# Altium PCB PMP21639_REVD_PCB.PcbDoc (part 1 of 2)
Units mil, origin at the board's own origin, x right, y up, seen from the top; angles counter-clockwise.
Board outline 3667.52 x 1155.04 mil, 4 copper layers (Top Layer, Signal Layer 1, Signal Layer 2, Bottom Layer), stack 90.224 mil thick; 122 components, 73 nets, 372 pads, 102 vias.
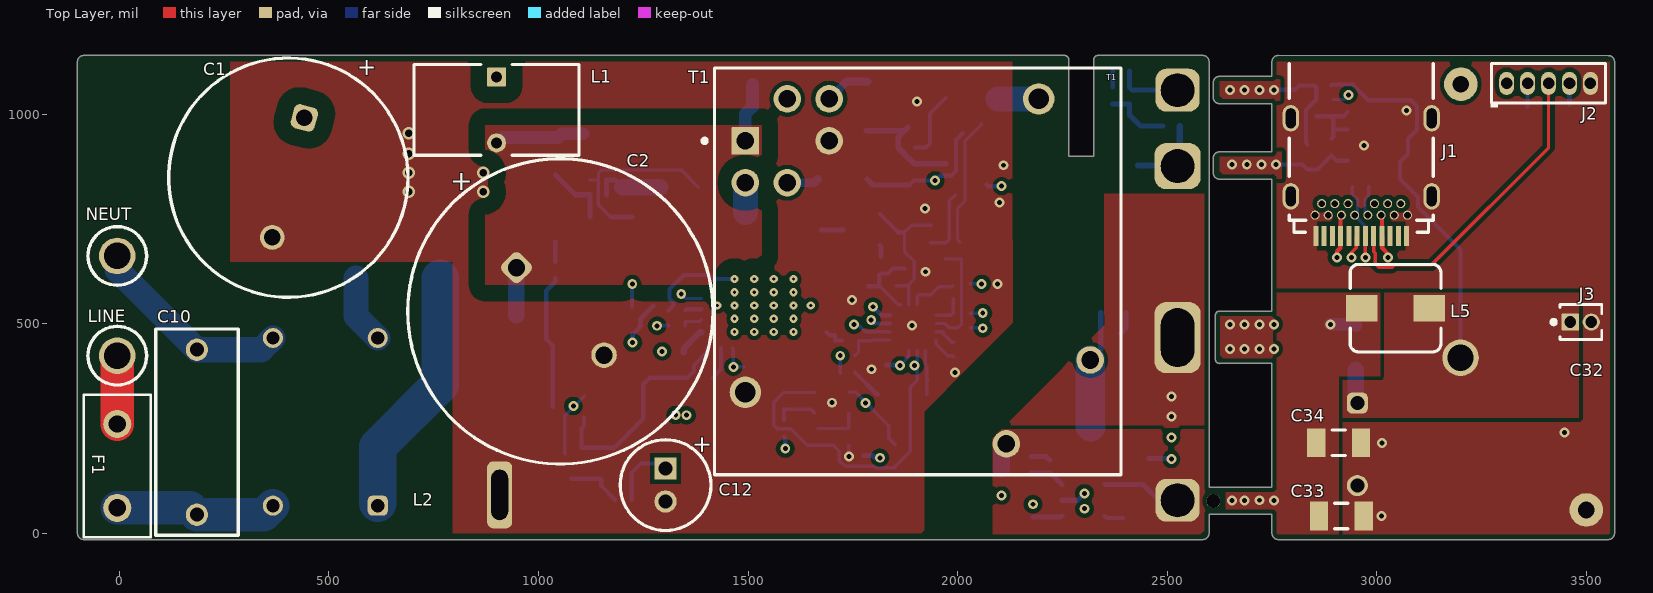
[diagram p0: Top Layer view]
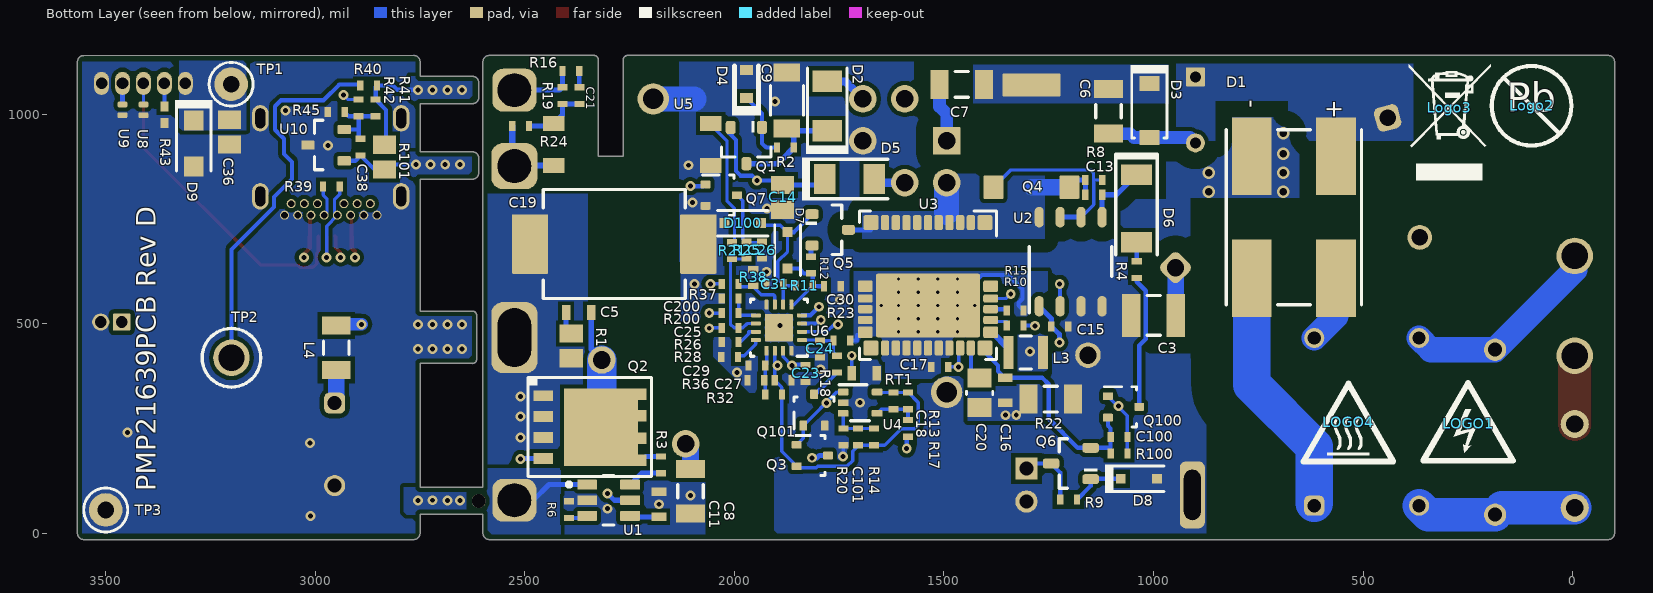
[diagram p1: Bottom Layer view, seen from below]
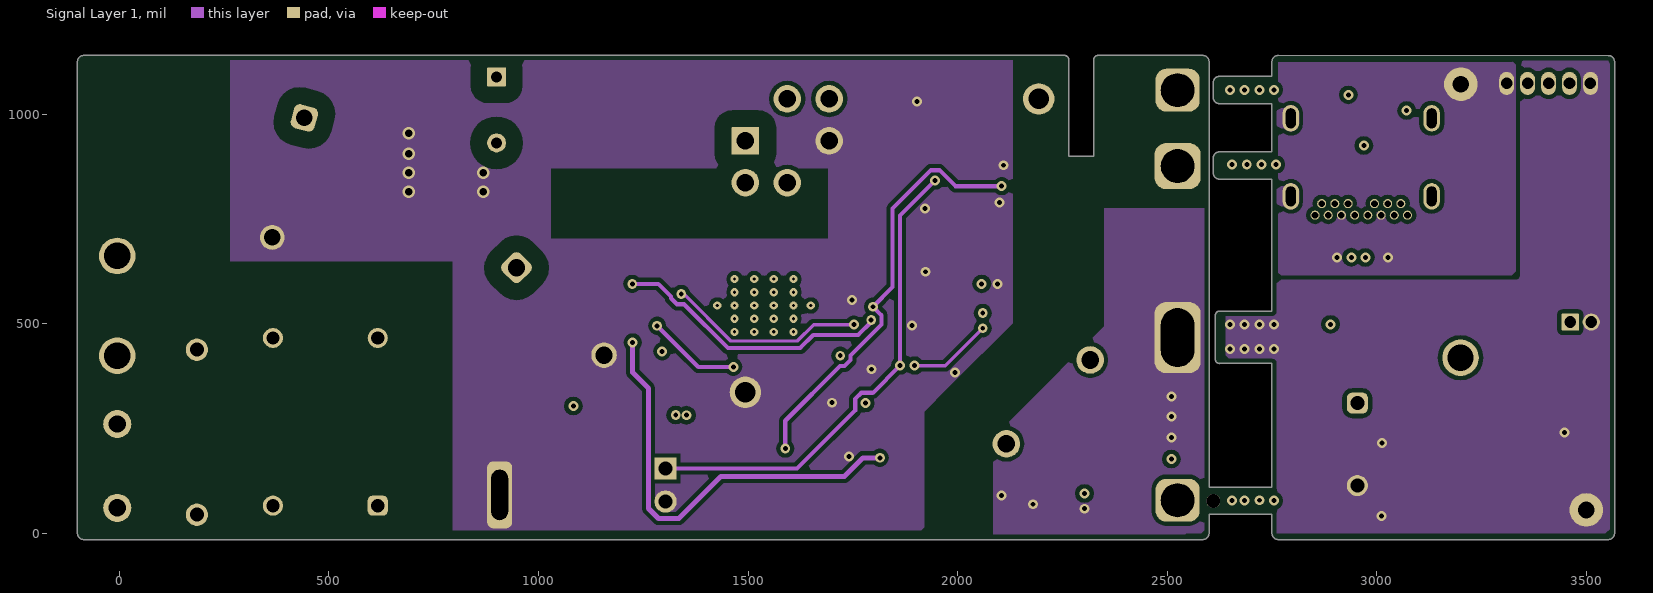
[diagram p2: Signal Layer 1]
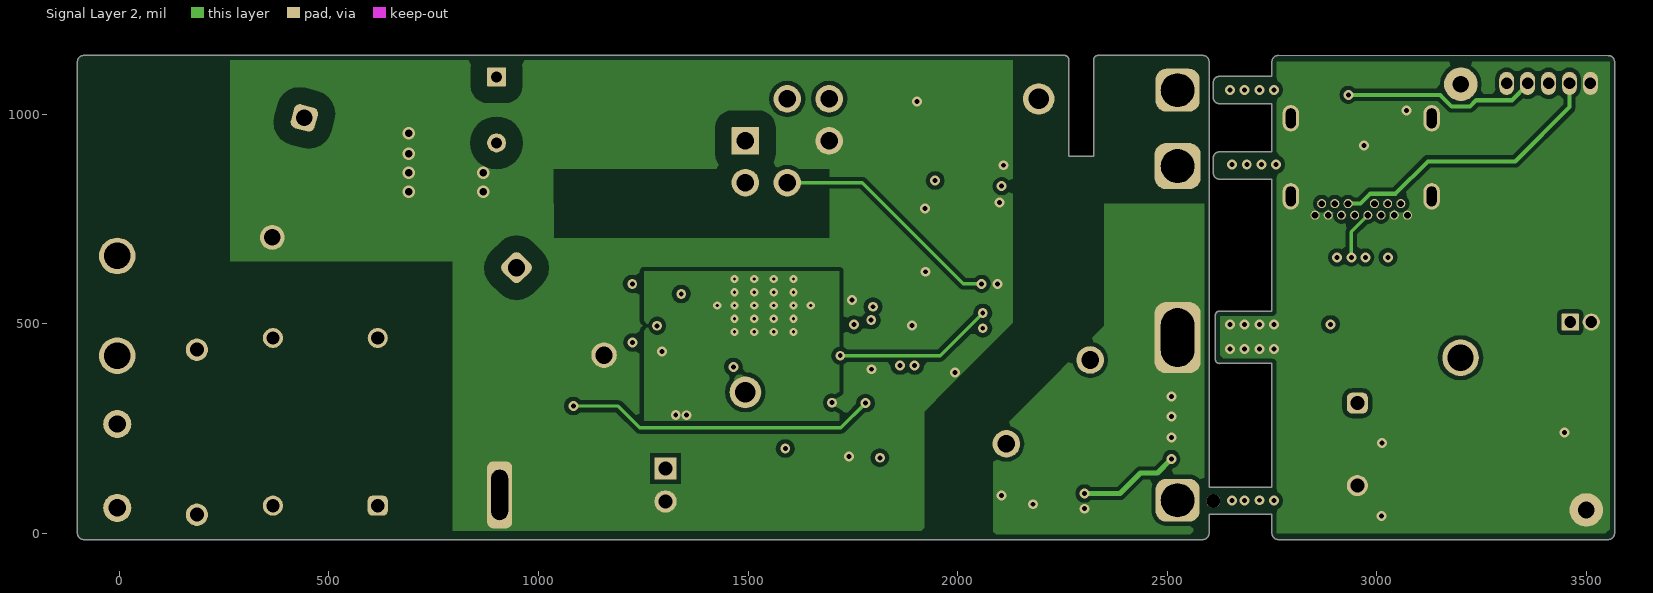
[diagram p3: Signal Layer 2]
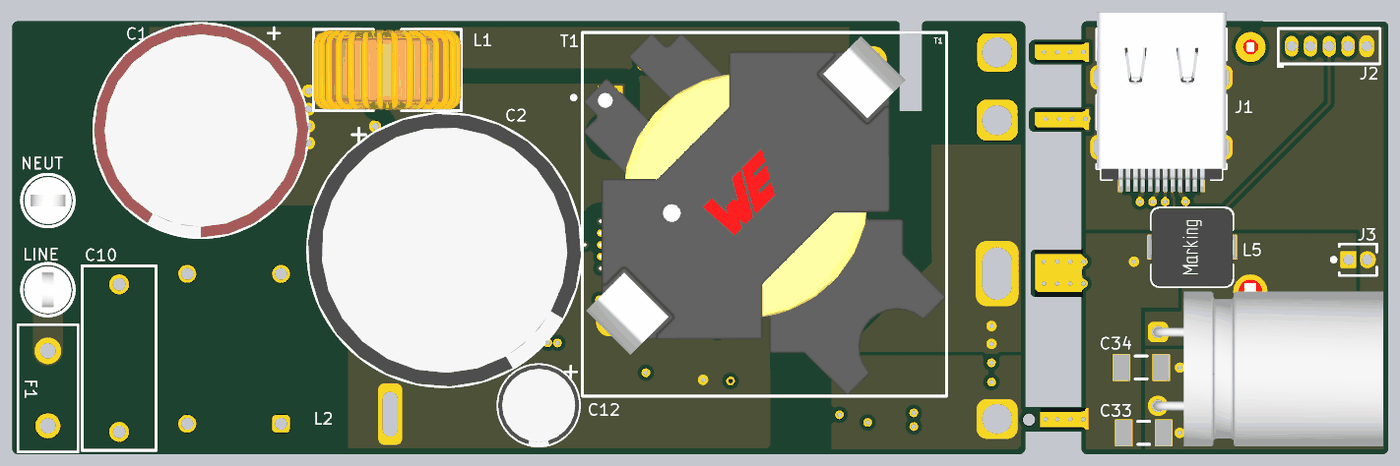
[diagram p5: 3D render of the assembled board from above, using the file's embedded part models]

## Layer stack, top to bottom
Top Solder: solder mask 0.4, Solder Resist, Dk 3.5
Top Layer: signal copper 2.7559
Dielectric 2: dielectric 10, Dk 4.2
Signal Layer 1: signal copper 2.7559
Dielectric 3: dielectric 10, Dk 4.2
Signal Layer 2: signal copper 2.7559
Dielectric1: core 59.2, FR-4, Dk 4.8
Bottom Layer: signal copper 2.7559
Bottom Solder: solder mask 0.4, Solder Resist, Dk 3.5

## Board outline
-85,-15.02 cw(c-85,0) -100.02,0 -100,0 -100,1125 -100.02,1125 cw(c-85,1125) -85,1140.02 2255,1140.02 cw(c2255,1130) 2265.02,1130 2265.02,900 2324.98,900 2324.98,1130 cw(c2335,1130) 2335.69,1139.99 2336.3,1140.02 2585,1140.02 cw(c2585,1125) 2600.02,1125 2600,1125 2600,110 2749.98,110 2749.98,405 2625,405 2625,404.98 cw(c2625,415) 2614.98,415 2614.98,520 cw(c2625,520) 2625,530.02 2625,530 2749.98,530 2749.98,845 2625,845 2625,844.98 cw(c2625,860) 2609.98,860 2609.98,895 cw(c2625,895) 2625,910.02 2625,910 2749.98,910 2749.98,1025 2625,1025 2625,1024.98 cw(c2625,1040) 2609.98,1040 2609.98,1075 cw(c2625,1075) 2625,1090.02 2625,1090 2749.98,1090 2749.98,1125 cw(c2765,1125) 2765,1140.02 3552.48,1139.64 cw(c3552.48,1124.62) 3567.5,1124.62 3567.5,0 cw(c3552.48,0) 3552.48,-15.02 2765,-15.02 cw(c2765,0) 2749.98,0 2749.98,45 2600,45 2600,0 2600.02,0 cw(c2585,0) 2585,-15.02

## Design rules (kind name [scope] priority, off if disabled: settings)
AcuteAngle [All] p1 off: minimum=4.50000000000000E+0001 checktracksonly=FALSE
AssemblyTestPointUsage [All] p1: valid=2
BoardOutlineClearance BoardOutlineClearance_MountingHoles [OnCopper and InComponentClass('Mounting Holes')] p1: gap=11.81 ignorepadtopadclearanceinfootprint=FALSE
BoardOutlineClearance BoardOutlineClearance_Poly [OnCopper and IsPoly] p2: gap=11.81 ignorepadtopadclearanceinfootprint=FALSE
BoardOutlineClearance [OnCopper and Not InComponentClass('Logo') and not InComponentClass('FiducialMark') and not InRegion(1000,500,4000,800) and not InPoly] p3: gap=10 ignorepadtopadclearanceinfootprint=FALSE
Clearance "Clearance VAC to PGND" [InNetClass('VAC') vs InNetClass('PGND')] p1: gap=100 ignorepadtopadclearanceinfootprint=TRUE
Clearance "Clearance VSW to HV" [InNetClass('Switch Node') vs InNetClass('High Voltage')] p2: gap=34 ignorepadtopadclearanceinfootprint=FALSE
Clearance Clearance_Safety [InNetClass('PGND') vs InNetClass('SGND')] p3: gap=160 ignorepadtopadclearanceinfootprint=FALSE
Clearance "Clearance VSW to PGND" [InNetClass('Switch Node') vs InNetClass('PGND')] p4: gap=34 ignorepadtopadclearanceinfootprint=FALSE
Clearance Clearance_HV [InNetClass('High Voltage') vs InNetClass('PGND')] p5: gap=40 ignorepadtopadclearanceinfootprint=FALSE
Clearance Clearance_Keepouts [((IsTrack Or IsArc) And Not InPoly) And IsFree and IsKeepOut vs ((IsTrack Or IsArc) And Not InPoly) And IsFree and IsKeepOut] p6: gap=0 ignorepadtopadclearanceinfootprint=FALSE
Clearance Clearance_Poly [InPolygon] p7: gap=10 ignorepadtopadclearanceinfootprint=FALSE except(0: Arc-Hole Track-Hole SMDPad-Hole THPad-Hole Via-Hole Fill-Hole Poly-Hole Region-Hole Text-Hole)
Clearance [All] p8: gap=7.87 ignorepadtopadclearanceinfootprint=TRUE except(0: Arc-Hole Track-Hole SMDPad-Hole THPad-Hole Via-Hole Fill-Hole Poly-Hole Region-Hole Text-Hole)
ComponentClearance ComponentClearance_MountingHoles_FiducialMarks [InComponentClass('Mounting Holes') vs InComponentClass('FiducialMark')] p1: gap=50 collisioncheckmode=3 verticalgap=10 showdistances=FALSE
ComponentClearance ComponentClearance_Shunt [InComponentClass('Header') vs InComponentClass('Shunt')] p2 off: gap=0 collisioncheckmode=3 verticalgap=0 showdistances=FALSE
ComponentClearance ComponentClearance_Logo [InComponentClass('Logo')] p3 off: gap=50 collisioncheckmode=3 verticalgap=10 showdistances=FALSE
ComponentClearance ComponentClearance_ScrewToNut [(HasFootprint('NY PMS 440 0025 PH')) vs (HasFootprint('Keystone_1902C'))] p4 off: gap=5 collisioncheckmode=3 verticalgap=10 showdistances=FALSE
ComponentClearance ComponentClearance_MountingHoles [InComponentClass('Mounting Holes')] p5 off: gap=250 collisioncheckmode=3 verticalgap=100000 showdistances=FALSE
ComponentClearance ComponentClearance_SmallPassives [HasFootprint('0201*') or HasFootprint('0402*') or HasFootprint('0508') or HasFootprint('0603*') or HasFootprint('0612') or HasFootprint('0805*') or HasFootprint('0815*') or HasFootprint('0830*') or HasFootprint('1206*') or HasFootprint('1210*') or HasFootprint('1808*') or HasFootprint('1812*') or HasFootprint('1825*') or HasFootprint('2010*') or HasFootprint('2220*') or HasFootprint('2225*') or HasFootprint('2512*') or HasFootprint('2728*') or HasFootprint('3518*') vs HasFootprint('0201*') or HasFootprint('0402*') or HasFootprint('0508') or HasFootprint('0603*') or HasFootprint('0612') or HasFootprint('0805*') or HasFootprint('0815*') or HasFootprint('0830*') or HasFootprint('1206*') or HasFootprint('1210*') or HasFootprint('1808*') or HasFootprint('1812*') or HasFootprint('1825*') or HasFootprint('2010*') or HasFootprint('2220*') or HasFootprint('2225*') or HasFootprint('2512*') or HasFootprint('2728*') or HasFootprint('3518*')] p6: gap=10 collisioncheckmode=3 verticalgap=10 showdistances=FALSE
ComponentClearance ComponentClearance_THtoSMT [IsThruComponent vs IsSMTComponent] p7: gap=10 collisioncheckmode=3 verticalgap=10 showdistances=FALSE
ComponentClearance ComponentClearance_THtoTH [IsThruComponent vs IsThruComponent] p8: gap=10 collisioncheckmode=3 verticalgap=30 showdistances=FALSE
ComponentClearance [All] p9: gap=-39.37 collisioncheckmode=3 verticalgap=-39.37 showdistances=FALSE
DiffPairsRouting [All] p1: maxlimit=100 minlimit=10 mostfreqgap=10 toplayer_minwidth=15 toplayer_maxwidth=15 toplayer_prefwidth=15 midlayer1_minwidth=15 midlayer1_maxwidth=15 midlayer1_prefwidth=15 midlayer2_minwidth=15 midlayer2_maxwidth=15 midlayer2_prefwidth=15 bottomlayer_minwidth=15 bottomlayer_maxwidth=15 bottomlayer_prefwidth=15 maxuncoupledlength=1000
FabricationTestPointUsage TestPointUsage [All] p1: valid=2 allowmultiple=FALSE
FabricationTestpoint Testpoint [All] p1: side=3 testpointundercomponent=TRUE minsize=40 maxsize=100 preferedsize=60 minholesize=0 maxholesize=40 preferedholesize=32 testpointgrid=1 allowsidetop=TRUE allowsidebottom=TRUE usegrid=TRUE gridtolerance=0.01
FanoutControl Fanout_LCC [IsLCC] p1: bgadir=Out bgaviamode=Centered fanoutstyle=Auto fanoutdirection=Alternating viagrid=1 // Fanout_LCC (Default Rule)
FanoutControl Fanout_BGA [IsBGA] p2: bgadir=Out bgaviamode=Centered fanoutstyle=Auto fanoutdirection=Alternating viagrid=1 // Fanout_BGA (Default Rule)
FanoutControl Fanout_Default [All] p4: bgadir=Out bgaviamode=Centered fanoutstyle=Auto fanoutdirection=Alternating viagrid=1 // Fanout_Default (Default Rule)
FanoutControl Fanout_Small [(CompPinCount < 5)] p5: bgadir=Out bgaviamode=Centered fanoutstyle=Auto fanoutdirection=OutThenIn viagrid=1 // Fanout_Small (Default Rule)
HoleSize [All] p1: absolutevalues=TRUE maxlimit=251 minlimit=7.87 maxpercent=80.000 minpercent=20.000
MinimumAnnularRing MinimumAnnularRing_ThermalPadVias [IsVia and InAnyComponent] p1: minimumring=5.91
MinimumAnnularRing [All] p2: minimumring=2.9
MinimumSolderMaskSliver MinimumSolderMaskSliver_Logo [InComponentClass('Logo') vs InComponentClass('Logo')] p1 off: minsoldermaskwidth=0.7
MinimumSolderMaskSliver [All] p2 off: minsoldermaskwidth=3.94
PlaneConnect [All] p1: planeconnectstyle=Relief reliefexpansion=10 reliefentries=4 reliefconductorwidth=10 reliefairgap=10
PolygonConnect [All] p1: connectstyle=Direct reliefconductorwidth=10 reliefentries=4 polygonreliefangle="90 Angle" airgapwidth=10
RoutingVias ThermalPadVias [IsVia and InAnyComponent] p1: holewidth=7.87 width=19.68 viastyle="Through Hole" minholewidth=7.87 minwidth=19.68 maxholewidth=12.99 maxwidth=23.62
RoutingVias [All] p2: holewidth=16 width=34 viastyle="Through Hole" minholewidth=7.87 minwidth=22 maxholewidth=40 maxwidth=65
SilkToBoardRegionClearance [Not ((IsComment or IsDesignator) And (Hide <> 'False')) and not InRegion(1000,500,4000,800)] p1:
SilkToSilkClearance SilkToSilkClearance_Pb-FreeLogo [(HasFootprint('Pb-Free_Overlay_Medium') OR HasFootprint('Pb-Free_Overlay_Small')) vs (HasFootprint('Pb-Free_Overlay_Medium') OR HasFootprint('Pb-Free_Overlay_Small'))] p1: silktosilkclearance=0
SilkToSilkClearance [All] p2: silktosilkclearance=1
SilkToSolderMaskClearance SilkToComponentPadClearance [(IsPad or IsFill or IsRegion) and InAnycomponent] p1: minsilkscreentomaskgap=0.1 clearancetoexposedcopper=TRUE
SilkToSolderMaskClearance "Silk to Solder Mask Opening" [All] p2: minsilkscreentomaskgap=0.1 clearancetoexposedcopper=FALSE
SolderMaskExpansion [All] p1: expansion=1.97
Width [All] p1: maxlimit=100 minlimit=6 preferedwidth=10 checkconnectedcopper=TRUE
15 further rules are at their usual default settings.

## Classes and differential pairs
net class VAC: NetC10_1 NetC10_2 NetD1_2 NetD1_3 NetF1_2
net class "Switch Node": NetC13_1 NetQ4_1 VSW
net class SGND: NetC5_1 NetC5_2 S1 SGND1
component class Header: J2 J3
component class PMP21639_REVD_pg2: C32 C33 C34 C36 C38 D9 J1 J2 J3 L4 L5 R39 R40 R41 R42 R43 R45 R101 TP1 TP2 TP3 U8 U9 U10
net class PGND: NetC16_2 PGND VS
net class "High Voltage": NetC1_1 NetC2_1 NetC6_2
component class PMP21639_REVD_pg1: C1 C2 C3 C5 C6 C7 C8 C9 C10 C11 C12 C13 C14 C15 C16 C17 C18 C19 C20 C21 C22 C23 C24 C25 C26 C27 C29 C30 C31 C100 C101 C200 D1 D2 D3 D4 D5 D6 D7 D8 D100 F1 L1 L2 L3 LINE LOGO1 Logo2 Logo3 LOGO4 NEUT Q1 Q2 Q3 Q4 Q5 Q6 Q7 Q100 Q101 R1 R2 R3 R4 R6 R8 R9 R10 R11 R12 R13 R14 R15 R16 R17 R18 R19 R20 R21 R22 R23 R24 R25 R26 R28 R32 R36 R37 R38 R100 R200 RT1 T1 U1 U2 U3 U4 U5 U6

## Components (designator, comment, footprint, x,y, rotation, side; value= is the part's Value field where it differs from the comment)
C1 "EKXJ401ELL390MU20S" Chemi-Con_1450x2000 403.05,848.39 r255 top value=39uF
C2 "400BXW68MEFC18X20" BXW_1800x2000 1052.06,529.4 r315 top value=68uF
C3 "C1210W104KCRACTU" 1210_230L 1000,520 r0 bottom value=0.1uF
C5 "C1608C0G2E221J080AA" 0603S 2371.54,526.5 r180 bottom value=220pF
C6 "CGA5L3X7T2E224K160AE" 1206L 1107.24,1006.66 r90 bottom value=0.22uF
C7 "CGA5L3X7T2E224K160AE" 1206L 1457.44,1071.13 r180 bottom value=0.22uF
C8 "C3216X5R1E336M160AC" 1206_180L 2105,100.39 r270 bottom value=33uF
C9 "C3216X7R2A474K160AA" 1206_180 1874.85,1032.74 r270 bottom value=0.47uF
C10 "BFC242042203" CAPRR1000W60L1250T500H1100 185,241.01 r270 top value=0.1uF
C11 "GRM188R61E105KA12D" 0603S 2180,69.2 r90 bottom value=1uF
C12 "ECA1HM220" Panasonic_500x1100 1303.15,115 r270 top value=22uF
C13 "GRM155R71E473KA88D" 0402S 1142.68,807.6 r0 bottom value=0.047uF
C14 "C2012X7R1H105K085AC" 0805L 1885,801.47 r90 bottom value=1uF
C15 "GRM155R71E103KA01D" 0402S 1223.8,493.78 r180 bottom value=0.01uF
C16 "GRM188R61E105KA12D" 0603S 1353.5,341.16 r270 bottom value=1uF
C17 "GRM155R71H223KA12D" 0402S 1510,397 r180 bottom value=0.022uF
C18 "GRM155R71C472KA01D" 0402S 1620,315.82 r270 bottom value=4700pF
C19 "DK1E3EA152M86RAH01" DK1_86 2286.81,690 r180 bottom value=1500pF
C20 "08053C225KAT2A" 0805_150 1415,335 r270 bottom value=2.2uF
C21 "GRM155R72A332KA01D" 0402S 2370,1044.1 r270 bottom value=3300pF
C23 "GRM155R61H104ME14D" 0402S 1830.29,381.46 r270 bottom value=0.1uF
C24 "GRM1555C1H101JA01D" 0402S 1795.86,439.68 r90 bottom value=100pF
C25 "GRM1555C1H101JA01D" 0402S 2010,490 r0 bottom value=100pF
C26 "GRM1555C1H180JA01D" 0402S 1934.2,675.32 r270 bottom value=18pF
C27 "C1005X7R1H104K050BB" 0402S 1883.82,365 r180 bottom value=0.1uF
C29 "C1005C0G1H221F050BA" 0402S 1946.22,400 r0 bottom value=220pF
C30 "GRM1555C1H220FA01D" 0402S 1766.34,589.25 r180 bottom value=22pF
C31 "GRM155R71H222KA01D" 0402S 1903.5,594.02 r0 bottom value=2200pF
C32 "687AVG025MGBJ" AVG_1000x1200_HU 2953.76,212.04 r270 top value=680uF
C33 "C3216X5R1E336M160AC" 1206_180L 2915.87,41.34 r0 top value=33uF
C34 "C3216X5R1E336M160AC" 1206_180L 2908.98,215.94 r0 top value=33uF
C36 "C2012X5R1E685K125AC" 0805L 3205,957.02 r270 bottom value=6.8uF
C38 "GRM155R71E103KA01D" 0402S 2891.99,921.12 r270 bottom value=0.01uF
C100 "GRM155R71H222KA01D" 0402S 1082.31,230.01 r180 bottom value=2200pF
C101 "GRM155R71H102KA01D" 0402S 1705,230 r90 bottom value=1000pF
C200 "GRM1555C1H101JA01D" 0402S 2010,560 r180 bottom value=100pF
D1 "Z4DGP406L-HF" Z4-D 665,754.17 r270 bottom value=600V
D2 "CSFMT104-HF" SOD-123H 1778.5,1019.33 r90 bottom value=200V
D3 "SMF100A" SOD-123FL 1010,1008.63 r270 bottom value=100V
D4 "CZRU52C15" SOD-523F 1971.14,1071.97 r90 bottom value=15V
D5 "CSFMT104-HF" SOD-123H 1725,845 r180 bottom value=200V
D6 "ES1JAF" SMAF 1040.62,775 r270 bottom value=600V
D7 "CDSOD323-T18C" SOD-323-Bi 1873.23,675 r90 bottom value=18V
D8 "13V" SOD-323 1035,130 r180 bottom
D9 "PMEG4030ER,115" SOD-123W 3290,929.96 r270 bottom value=40V
D100 "CDSOD323-T18C" SOD-323-Bi 1980.32,740 r180 bottom value=18V
F1 "39213150000" FUSE_392 -5,160.5 r90 top
J1 "632 723 300 011" Wurth_632_723_300_011 2963.11,1125.83 r180 top
J2 "GRPB051VWVN-RC" Sullins_GRPB051VWVN-RC 3410,1073.49 r0 top
J3 "GRPB021VWVN-RC" Sullins_GRPB021VWVN-RC 3486.93,503.77 r0 top
L1 "7447052" FP-7447052_PTH_D10MM0-MFG 900,1010 r0 top
L2 "RLTI-1301" Renco_RLTI-1301 491.5,265.83 r180 top value=1.3mH
L3 "BRC2518T220K" 1007 1305,431.22 r0 bottom value=22uH
L4 "74479136" 1206L 2950,442.4 r270 bottom value=0.68uH
L5 "744316100" WE-HCI_5040 3045,536.93 r90 top value=1uH
LINE "5012" Keystone5012 -5,423.61 r0 top
LOGO1 "DANGER HIGH VOLTAGE" IEC_HighVoltage_Small 249.51,260.9 r180 bottom
Logo2 "Pb-Free Symbol" Pb-Free_Overlay_Medium 98,1020 r180 bottom
Logo3 "WEEE logo" WEEE_Minimum 295,1015 r180 bottom
LOGO4 "CAUTION HOT SURFACE" IEC_HotSurface_Small 535,264.51 r180 bottom
NEUT "5012" Keystone5012 -5,661.66 r90 top
Q1 "BSS123" SOT-23L 1971.61,925.05 r270 bottom value=100V
Q2 "BSC093N15NS5ATMA1" PG-TDSON-8 2345,253.34 r180 bottom value=150V
Q3 "BSS223PWH6327" SOT-323 1814.04,185.44 r180 bottom value=-20V
Q4 "IPN60R1K0CEATMA1" FP-IPN60R1K0CEATMA1_SOT223-3-MFG 1291.22,947.6 r90 bottom
Q5 "BSS126H6327XTSA2" SOT-23L 1771.22,723.93 r180 bottom value=600V
Q6 "BSS138" SOT-23 1197.24,166.42 r0 bottom value=50V
Q7 "2N7002KW" SOT-323 2031.45,806.67 r180 bottom value=60V
Q100 "BSS223PWH6327" SOT-323 1071.53,301.49 r180 bottom value=-20V
Q101 "2N7002KW" SOT-323 1810,294.18 r90 bottom value=60V
R1 "CRCW080522R0JNEA" 0805L 2389.17,447.17 r270 bottom value=22
R2 "CRCW040249K9FKED" 0402S 1878.21,920 r0 bottom value=49.9k
R3 "CRCW0402301RFKED" 0402S 2175,163.19 r90 bottom value=301
R4 "CRCW04024R70JNED" 0402S 1040,628.79 r90 bottom value=4.7
R6 "CRCW040275K0FKED" 0402S 2394.8,56.62 r90 bottom value=75.0k
R8 "ERJ-2RKF1503X" 0402S 1142.68,842.81 r180 bottom value=150k
R9 "RC0402FR-0730K1L" 0402S 1202.76,80 r0 bottom value=30.1k
R10 "RC0402FR-0710KL" 0402S 1330,495.35 r180 bottom value=10.0k
R11 "RC0402FR-071ML" 0402S 1833.19,590.59 r0 bottom value=1.00Meg
R12 "CRCW0402121RFKED" 0402S 1816.89,640 r90 bottom value=121
R13 "CRCW04021M00FKED" 0402S 1585.55,315.82 r90 bottom value=1.00Meg
R14 "CRCW04021M00FKED" 0402S 1666.67,230 r270 bottom value=1.00Meg
R15 "ERJ-2RKF1503X" 0402S 1330,531.57 r0 bottom value=150k
R16 "CRCW0402825RFKED" 0402S 2390,1103.1 r180 bottom value=825
R17 "CRCW0402511KFKED" 0402S 1585.55,250 r270 bottom value=511k
R18 "CRCW04021K00FKED" 0402S 1755,403.61 r270 bottom value=1.00k
R19 "CRCW04028K25FKED" 0402S 2410,1044.04 r90 bottom value=8.25k
R20 "CRCW04021M00FKED" 0402S 1740,230 r90 bottom value=1.00Meg
R21 "CRCW040220K0FKED" 0402S 2005.59,674.42 r90 bottom value=20.0k
R22 "ERJ-8BSFR15V" 1206L 1245,320 r0 bottom value=0.15
R23 "CRCW04021K00FKED" 0402S 1743.66,460 r180 bottom value=1.00k
R24 "CRCW040234K0FKED" 0402S 2510,971.37 r180 bottom value=34.0k
R25 "CRCW0402511KFKED" 0402S 1971.14,675.32 r270 bottom value=511k
R26 "CRCW0402383KFKED" 0402S 2010.44,455.83 r180 bottom value=392k
R28 "CRCW040282K5FKED" 0402S 2011.45,420.81 r0 bottom value=82.5k
R32 "CRCW0402191KFKED" 0402S 1906.65,331.31 r0 bottom value=191k
R36 "CRCW040234K0FKED" 0402S 1948.62,365 r180 bottom value=34.0k
R37 "CRCW040269K8FKED" 0402S 2010,595 r180 bottom value=69.8k
R38 "ERJ-2RKF1002X" 0402S 1955.02,610.2 r270 bottom value=10.0k
R39 "CRCW0402100RFKED" 0402S 2961.36,827 r0 bottom value=100
R40 "RC0402JR-070RL" 0402S 2872.61,1068.17 r0 bottom value=0
R41 "ERJ-2RKF1503X" 0402S 2855.83,1015 r90 bottom value=150k
R42 "CRCW040224K9FKED" 0402S 2896.6,1014.79 r270 bottom value=24.9k
R43 "CRCW040215K0FKED" 0402L 3360,998.85 r90 bottom value=15.0k
R45 "ERJ-2RKF1503X" 0402S 2950,1004.75 r0 bottom value=150k
R100 "CRCW0402511KFKED" 0402S 1082.31,190 r0 bottom value=511k
R101 "CRCW08052K00JNEA" 0805L 2835,897.55 r270 bottom value=2.0k
R200 "CRCW04027K50FKED" 0402S 2010,525 r180 bottom value=7.50k
RT1 "NCP18WB473J03RB" 0603S 1690,381.85 r0 bottom value=47k
T1 "750318555" FP-750318555_PTH_TRANSFORMER_24MM64_24MM64-MFG 1905,624.89 r0 top
TP1 "5000" Keystone5000 3200.75,1071.31 r180 bottom
TP2 "Vout" Keystone5010 3200,418.74 r180 bottom
TP3 "5001" Keystone5001 3500,55.59 r90 bottom
U1 "MP6908GJ-Z" FP-MP6908GJ-Z_TSOT23-6-MFG 2300,78.74 r180 bottom
U2 "UCC5350SBDR" D0008B_L 1197.84,647.87 r90 bottom
U3 "LMG3411R150RWHR" RWH0032A 1538.19,591.62 r270 bottom
U4 "TLV7021DCKR" DCK0005A_L 1700,311.42 r180 bottom
U5 "VOL618A-2T" SOP254P1020X230-4 2243.53,927.49 r180 bottom
U6 "UCC28780RTER" RTE0016C_NV 1893.66,490.47 r0 bottom
U8 "TPD1E05U06QDPYRQ1" DPY0002A 3410,1010 r270 bottom
U9 "TPD1E05U06QDPYRQ1" DPY0002A 3460,1010.26 r270 bottom
U10 "ATL431AIDBZR" DBZ0003A_L 2974.23,926.08 r0 bottom

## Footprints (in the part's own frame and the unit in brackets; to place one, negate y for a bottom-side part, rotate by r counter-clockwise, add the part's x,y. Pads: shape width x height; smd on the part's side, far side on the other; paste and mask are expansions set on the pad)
0402L [mm] "0402 from SM-752 data"
  rect 0.6x0.5 smd: 1(-0.5,0) 2(0.5,0)
  body extent -0.55,-0.3 0.55,0.3, height 0.6
0402S [mil] "Based on C0402S footprint from PADS legacy"
  rect 15x24 smd: 1(-20,0) 2(20,0)
  body extent -22,-12 22,12, height 24
0603S [mil]
  rect 20x35 smd: 1(-30,0) 2(30,0)
  body extent -34,-19 34,19, height 39
0805_150 [mm] "0805 / 1.5 mm height"
  rect 1.15x1.45 smd: 1(-0.9,0) 2(0.9,0)
  silkscreen extent -0.1,-0.8 0.1,0.8, body extent -1.1,-0.72 1.1,0.72, height 1.5
0805L [mm] "0805 from SM-752 data"
  rect 1.1x1.4 smd: 1(-0.75,0) 2(0.75,0)
  body extent -1.1,-0.72 1.1,0.72, height 1.45
1007 [mm] "SMD, 2-Leads, Body 2.5x1.8mm"
  rect 0.6x2 smd: 1(-1.05,0) 2(1.05,0)
  silkscreen extent -0.35,-1 0.35,1, body extent -1.35,-1 1.35,1, height 2
1206_180 [mm] "1206_180"
  rect 1.1x1.6 smd: 1(-1.7,0) 2(1.7,0)
  silkscreen extent -0.9,-1 0.9,1, body extent -1.75,-0.95 1.75,0.95, height 1.8
1206_180L [mm] "1206_180"
  rect 1.1x1.75 smd: 1(-1.35,0) 2(1.35,0)
  silkscreen extent -0.4,-0.77 0.4,0.77, body extent -1.75,-0.95 1.75,0.95, height 1.8
1206L [mm] "1206 from SM-752 data"
  rect 1.1x1.75 smd: 1(-1.35,0) 2(1.35,0)
  silkscreen extent -0.4,-0.77 0.4,0.77, body extent -1.7,-0.9 1.7,0.9, height 1.35
1210_230L [mm] "1210"
  rect 1.1x2.6 smd: 1(-1.35,0) 2(1.35,0)
  silkscreen extent -0.4,-1.2 0.4,1.2, body extent -1.7,-1.35 1.7,1.35, height 2.3
AVG_1000x1200_HU [mm] "TH, 2-Leads, Dia 10mm, Pin Spacing 5mm"
  rrect50% 1.275x1.275 hole 0.85: 1(-2.5,0)
  round 1.275 hole 0.85: 2(2.5,0)
  body extent -5.25,-0.31 5.25,15.25, height 10.5
BXW_1800x2000 [mm] "TH, 2-Leads, Dia 18mm, Pin Spacing 7.5mm"
  rrect50% 1.55x1.55 hole 1.05: 1(-3.75,0)
  round 1.55 hole 1.05: 2(3.75,0)
  silkscreen extent -9.25,-9.25 9.25,9.25, body extent -9.25,-9.25 9.26,9.25, height 22.01
CAPRR1000W60L1250T500H1100 [mm] "Vishay BC Components"
  round 1.35 hole 0.85: 1(-5,0) 2(5,0)
  silkscreen extent -6.25,-2.5 6.25,2.5, body extent -6.25,-2.5 6.25,2.5, height 11
Chemi-Con_1450x2000 [mm] "TH, 2-Leads, Dia 14.5mm"
  rrect50% 1.5x1.5 hole 1: 1(-3.75,0)
  round 1.5 hole 1: 2(3.75,0)
  silkscreen extent -7.25,-7.25 7.25,7.25, body extent -7.25,-7.25 7.26,7.25, height 21.51
D0008B_L [mm] "SOIC, 8-Leads, Body 4.9x3.9mm, Pitch 1.27mm, IPC High Density"
  oval 1.25x0.55 smd: 1(-2.7,1.905) 2(-2.7,0.635) 3(-2.7,-0.635) 4(-2.7,-1.905) 5(2.7,-1.905) 6(2.7,-0.635) 7(2.7,0.635) 8(2.7,1.905)
  silkscreen extent -3.1,-2.5 0.9,2.5, body extent -3,-2.45 3,2.45, height 1.63
DBZ0003A_L [mm] "SOT23, 3-Leads, Body 2.9x1.3mm, Pitch 0.95mm, Lead Span 2.4mm, IPC High Density"
  rrect18% 0.8x0.55 smd: 1(-1.1,0.95) 2(-1.1,-0.95) 3(1.1,0)
  silkscreen extent 0.2,-1.5 0.7,1.5, body extent -1.26,-1.46 1.26,1.46, height 0.98
DCK0005A_L [mm] "SOT353, 5-Leads, Body 2x1.3mm, Pitch 0.65mm, Lead Span 2.1mm, IPC High Density"
  rrect25% 0.65x0.4 smd: 1(-1.025,0.65) 2(-1.025,0) 3(-1.025,-0.65) 4(1.025,-0.65) 5(1.025,0.65)
  silkscreen extent -1.27,-1.09 0.56,1.09, body extent -1.14,-1 1.14,1, height 0.95
DK1_86 [mm] "SMD, 2-Leads, Body 8x6mm"
  rrect5% 2.2x3.6 smd: 1(-5.1,0) 2(5.1,0)
  silkscreen extent -4.3,-3.3 4.3,3.3, body extent -5.95,-3.25 5.95,3.25, height 2.5
DPY0002A [mm] "X1SON-2"
  rrect57% 0.35x0.6 smd paste-0.5 mask-0.05: 1(-0.325,0) 2(0.325,0)
  rrect33% 0.3x0.5 on Bottom Paste: 1S(-0.35,0) 2S(0.35,0)
  body extent -0.5,-0.3 0.5,0.3, height 0.45
FP-7447052_PTH_D10MM0-MFG [mm]
  rrect9% 1.15x1.15 hole 0.65 paste-1000 mask+0: 1(0,2)
  round 1.15 hole 0.65 paste-1000 mask+0: 2(0,-2)
  silkscreen extent -5,-2.75 5,2.75, body extent -5.1,-2.85 5.1,2.85, height 0.25
FP-750318555_PTH_TRANSFORMER_24MM64_24MM64-MFG [mm]
  rrect6% 1.67x1.67 hole 1.07 paste-1000 mask+0: 1(-10.45,7.91)
  round 1.67 hole 1.07 paste-1000 mask+0: 2(-10.45,5.37) 3(-7.91,5.37) 4(5.37,-10.45) 7(10.45,-5.37) 8(-5.37,7.91) 9(-5.37,10.45) 10(-7.91,10.45)
  round 1.9 hole 1.25 paste-1000 mask+0: 11(7.33,10.45) 12(-10.45,-7.33)
  silkscreen extent -13.04,-12.32 12.32,12.32, body extent -12.42,-12.42 12.42,12.42, height 0.25
FP-IPN60R1K0CEATMA1_SOT223-3-MFG [mm]
  rrect8% 1.4x1.2 smd paste+0 mask+0: 1(-3.1,2.3) 3(-3.1,-2.3)
  rrect7% 1.4x3.5 smd paste+0 mask+0: 2(3.1,0)
  body extent -3.5,-3.25 3.52,3.25, height 1.8
FP-MP6908GJ-Z_TSOT23-6-MFG [mm]
  rrect17% 1.2x0.6 smd paste+0 mask+0: 1(-1.3,0.95) 2(-1.3,0) 3(-1.3,-0.95) 4(1.3,-0.95) 5(1.3,0) 6(1.3,0.95)
  silkscreen extent -2.53,-1.5 0.33,1.5, body extent -1.4,-1.45 1.4,1.45, height 1
FUSE_392 [mm] "LITTELFUSE"
  round 1.7 hole 1.05: 1(-2.54,0) 2(2.54,0)
  silkscreen extent -4.32,-2.03 4.32,2.03, body extent -4.25,-2 4.25,2, height 8
IEC_HighVoltage_Small [mil]
  silkscreen extent -107,-88 107,97
IEC_HotSurface_Small [mil]
  silkscreen extent -107,-93 107,92
Keystone5000 [mil] "For Keystone 500x miniature loop terminals"
  round 80 hole 40: 1(0,0)
  silkscreen extent -52,-52 52,52, body extent -49,-49 49,49, height 182
Keystone5001 [mil] "For Keystone 500x miniature loop terminals"
  round 80 hole 40: 1(0,0)
  silkscreen extent -52,-52 52,52, body extent -49,-49 49,49, height 182
Keystone5010 [mil] "Keystone Multipurpose loops"
  round 87 hole 63: 1(0,0)
  silkscreen extent -70,-70 70,70, body extent -63,-63 63,62, height 319
Keystone5012 [mil] "Keystone Multipurpose loops"
  round 87 hole 63: 1(0,0)
  silkscreen extent -70,-70 70,70, body extent -63,-63 63,62, height 319
Panasonic_500x1100 [mm] "TH, 2-Leads, Dia 5mm,  Lead Spacing 2mm"
  rect 1.35x1.35 hole 0.85: 1(-1,0)
  round 1.35 hole 0.85: 2(1,0)
  silkscreen extent -2.75,-2.75 2.75,2.75, body extent -2.73,-2.75 2.75,2.75, height 12.51
Pb-Free_Overlay_Medium [mil]
  silkscreen extent -95,-95 95,95
PG-TDSON-8 [mm] "Infineon recommended land pattern"
  rect 1.2x0.65 smd: 1(-2.825,1.905) 2(-2.825,0.635) 3(-2.825,-0.635) 4(-2.825,-1.905)
  rect 0.5x0.7 smd: 5(3.175,-2) 6(3.175,-0.675) 7(3.175,0.675) 8(3.175,2)
  rect 4.5x4.7 smd paste-2.25: 9(0.675,0)
  silkscreen extent -3.74,-3 3.74,3, body extent -3.18,-2.89 3.18,2.9, height 1.1
Renco_RLTI-1301 [mil] "TH, 4-Leads, Body 15.24x9.906mm"
  rrect50% 48x48 hole 32: 1(-125,200)
  round 48 hole 32: 2(125,200) 3(-125,-200) 4(125,-200)
  body extent -195,-300 195,300, height 725
RTE0016C_NV [mm] "Texas Insturments"
  rrect42% 0.6x0.24 smd: 1(-1.4,0.75) 2(-1.4,0.25) 3(-1.4,-0.25) 4(-1.4,-0.75) 9(1.4,-0.75) 10(1.4,-0.25) 11(1.4,0.25) 12(1.4,0.75)
  rrect42% 0.24x0.6 smd: 5(-0.75,-1.4) 6(-0.25,-1.4) 7(0.25,-1.4) 8(0.75,-1.4) 13(0.75,1.4) 14(0.25,1.4) 15(-0.25,1.4) 16(-0.75,1.4)
  rrect6% 1.55x1.55 on Bottom Paste: 17(0,0)
  rrect6% 1.68x1.68 smd paste-0.85: 17(0,0)
  silkscreen extent -1.72,-1.73 1.72,1.73, body extent -1.57,-1.57 1.58,1.58, height 0.81
RWH0032A [mm] "VQFN, 32-Lead, Body 8x8mm"
  rrect22% 0.9x0.9 smd paste-0.07 mask-0.05: 1(-3.8,3.45) 11(-3.8,-3.45) 17(3.8,-3.45) 27(3.8,3.45)
  rrect40% 0.9x0.5 smd paste-0.05 mask-0.05: 2(-3.8,2.6) 3(-3.8,1.95) 4(-3.8,1.3) 5(-3.8,0.65) 6(-3.8,0) 7(-3.8,-0.65) 8(-3.8,-1.3) 9(-3.8,-1.95) 10(-3.8,-2.6) 18(3.8,-2.6) 19(3.8,-1.95) 20(3.8,-1.3) 21(3.8,-0.65) 22(3.8,0) 23(3.8,0.65) 24(3.8,1.3) 25(3.8,1.95) 26(3.8,2.6)
  rrect29% 0.7x0.9 smd paste-0.05 mask-0.05: 12(0.05,-3.8) 16(2.85,-3.8) 28(2.85,3.8) 32(0.05,3.8)
  rrect40% 0.5x0.9 smd paste-0.05 mask-0.05: 13(0.8,-3.8) 14(1.45,-3.8) 15(2.1,-3.8) 29(2.1,3.8) 30(1.45,3.8) 31(0.8,3.8)
  rrect10% 1.6x0.99 on Bottom Paste: 33(0.314,-2.38) 33(0.314,-1.19) 33(0.314,0) 33(0.314,1.19) 33(0.314,2.38) 33(2.114,-2.38) 33(2.114,-1.19) 33(2.114,0) 33(2.114,1.19) 33(2.114,2.38)
  rrect5% 3.85x6.3 smd paste-2 mask-0.05: 33(1.225,0)
  silkscreen extent -4.5,-4.15 4.5,4.15, body extent -4,-4 4,4, height 0.9
SMAF [mm] "SMD, 2-Leads, Body 3.8x2.5mm"
  rect 1.24x1.89 smd: 1(-2.04,0) 2(2.04,0)
  silkscreen extent -3.4,-1.3 2.8,1.3, body extent -2.35,-1.25 2.35,1.25, height 1
SOD-123FL [mm] "Copied from SOD-123"
  rect 0.915x1.22 smd: 1(-1.637,0) 2(1.637,0)
  silkscreen extent -2.74,-1.16 1.68,1.16, body extent -1.9,-0.9 1.9,0.9, height 1
SOD-123H [mm] "SMT, 2-Leads, Body 3.5x1.6mm"
  rect 1.3x1.8 smd: 1(-1.5,0) 2(1.5,0)
  silkscreen extent -2.9,-1.3 2.3,1.3, body extent -1.9,-0.9 1.9,0.9, height 1
SOD-123W [mm] "NXP recommended land pattern"
  rect 1.2x1.2 smd paste-0.05: 1(-1.4,0) 2(1.4,0)
  silkscreen extent -2.64,-1.14 1.68,1.14, body extent -1.85,-0.95 1.85,0.95, height 1.1
SOD-323 [mm] "NXP recommended land pattern"
  rect 0.6x0.6 smd paste-0.05: 1(-1.1,0) 2(1.1,0)
  silkscreen extent -2.06,-0.86 1.53,0.86, body extent -1.3,-0.67 1.3,0.68, height 1.1
SOD-323-Bi [mm] "SOD323, 2-Leads, Body 1.9x1.45mm, No Polarity Mark"
  rect 0.6x0.6 smd paste-0.05: 1(-1.1,0) 2(1.1,0)
  silkscreen extent -1.53,-0.77 1.53,0.77, body extent -1.27,-0.65 1.27,0.65, height 1.02
SOD-523F [mm] "COMCHIP"
  rect 0.6x0.8 smd paste-0.05: 1(-0.85,0) 2(0.85,0)
  silkscreen extent -1.92,-0.87 1.1,0.88, body extent -0.9,-0.5 0.9,0.5, height 0.85
SOP254P1020X230-4 [mm] "VISHAY"
  rect 1.3x0.9 smd: 1(-4.75,1.27) 2(-4.75,-1.27) 3(4.75,-1.27) 4(4.75,1.27)
  body extent -3.85,-2.05 3.85,2.05, height 2.02
SOT-23 [mm] "SOT23, 3-Leads, Body 2.9x1.3mm, Pitch 0.95mm, Lead Span 2.5mm, IPC Medium Density"
  rrect50% 1x0.6 smd: 1(-1.2,0.95) 2(-1.2,-0.95) 3(1.2,0)
  silkscreen extent -1.62,-1.5 0.7,1.5, body extent -1.16,-1.45 1.21,1.45, height 1
SOT-23L [mm] "SOT23, 3-Leads, Body 2.9x1.3mm, Pitch 0.95mm, Lead Span 2.5mm, IPC High Density"
  rrect50% 0.8x0.6 smd: 1(-1.1,0.95) 2(-1.1,-0.95) 3(1.1,0)
  silkscreen extent -1.5,-1.5 0.7,1.5, body extent -1.16,-1.45 1.21,1.45, height 1
SOT-323 [mm] "Diodes Inc recommended land pattern.  2016-02-24"
  rrect21% 0.6x0.47 smd: 1(-0.95,0.65) 2(-0.95,-0.65) 3(0.95,0)
  silkscreen extent -1.14,-1.22 0.77,1.22, body extent -1.13,-1.13 1.12,1.12, height 1.13
Sullins_GRPB021VWVN-RC [mil] "Sullins"
  rrect10% 41x41 hole 28: 1(-25,0)
  round 41 hole 28: 2(25,0)
  silkscreen extent -70,-42 50,42, body extent -50,-42 50,42, height 157
Sullins_GRPB051VWVN-RC [mm] "SULLINS"
  oval 0.9x1.4 hole 0.7: 1(-2.54,0) 2(-1.27,0) 3(0,0) 4(1.27,0) 5(2.54,0)
  silkscreen extent -3.52,-1.47 3.45,1.2, body extent -3.42,-1.17 3.42,1.17, height 4.2
WE-HCI_5040 [mm] "SMD, 2-Leads, Body 5.5x5.3mm"
  rect 1.6x1.9 smd: 1(0,2.05) 2(0,-2.05)
  silkscreen extent -2.65,-2.75 2.65,2.75, body extent -2.65,-2.79 2.65,2.79, height 3.95
WEEE_Minimum [mil] "WEEElie bin"
  silkscreen extent -95,-172 99,104
Wurth_632_723_300_011 [mm] "Connector, Receptacle, USB Type C, R/A"
  rect 0.3x1.2 smd: A1(-2.75,10.58) A2(-2.25,10.58) A3(-1.75,10.58) A4(-1.25,10.58) A5(-0.75,10.58) A6(-0.25,10.58) A7(0.25,10.58) A8(0.75,10.58) A9(1.25,10.58) A10(1.75,10.58) A11(2.25,10.58) A12(2.75,10.58)
  round 0.55 hole 0.4: B1(2.8,9.32) B2(2.4,8.62) B3(1.6,8.62) B4(1.2,9.32) B5(0.8,8.62) B6(0.4,9.32) B7(-0.4,9.32) B8(-0.8,8.62) B9(-1.2,9.32) B10(-1.6,8.62) B11(-2.4,8.62) B12(-2.8,9.32) M1(2,9.32) M2(-2,9.32)
  rrect100% 1x1.6 hole 0.6 slot 1.2 at 90 deg: S1(-4.27,8.18) S2(-4.27,3.45) S3(4.27,3.45) S4(4.27,8.18)
  silkscreen extent -4.37,0.15 4.37,10.36, body extent -4.37,-0.96 4.37,10.83, height 3.07
Z4-D [mm] "SMD, 4-Leads, Body 8.1x10.5mm"
  rect 4.7x2.4 smd: 1(-3.7,2.55) 2(3.7,2.55) 3(3.7,-2.55) 4(-3.7,-2.55)
  silkscreen extent -5.3,-4.1 5.3,4.1, body extent -5.3,-4.1 5.3,4.1, height 1.56

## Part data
C1: library part CMP-0067531-1, "CAP, AL, 39 µF, 400 V, +/- 20%, AEC-Q200 Grade 2, TH", Cap_Case=14.5X20mm, Manufacturer=Chemi-Con, Supplier Part Number 1=565-3520-ND, Tolerance_%=20%, Value1=Unknown, Value2=400V, ValueDisplayed=39µF
C2: library part CMP-0009972-1, "CAP, AL, 68 uF, 400 V, +/- 20%, TH", Cap_Case=18x20mm, Manufacturer=Rubycon, Supplier Part Number 1=1189-1322-ND, Tolerance_%=20%, Value1=Unknown, Value2=400V, ValueDisplayed=68uF
C3: library part CMP-0009094-1, "CAP, CERM, 0.1 uF, 500 V, +/- 10%, X7R, 1210", Cap_Case=1210, Manufacturer=Kemet, Supplier Part Number 1=399-6508-1-ND, TempCo=X7R, Tolerance_%=10%, Value1=Unknown, Value2=500V, ValueDisplayed=0.1uF
C5: library part CMP-0006996-4, "CAP, CERM, 220 pF, 250 V, +/- 5%, C0G/NP0, 0603", Cap_Case=0603, Manufacturer=TDK, Supplier Part Number 1=445-2316-1-ND, TempCo=C0G/NP0, Tolerance_%=5%, Value1=Unknown, Value2=250V, ValueDisplayed=220pF
C6 C7: library part CMP-0008793-2, "CAP, CERM, 0.22 uF, 250 V, +/- 10%, X7T, AEC-Q200 Grade 1, 1206", Cap_Case=1206, Manufacturer=TDK, Supplier Part Number 1=445-8798-1-ND, TempCo=X7T, Tolerance_%=10%, Value1=Unknown, Value2=250V, ValueDisplayed=0.22uF
C8 C33 C34: library part CMP-0008655-2, "CAP, CERM, 33 uF, 25 V, +/- 20%, X5R, 1206", Cap_Case=1206_180, Manufacturer=TDK, Supplier Part Number 1=445-8046-1-ND, TempCo=X5R, Tolerance_%=20%, Value1="0.002648 ohm", Value2=25V, ValueDisplayed=33uF
C9: library part CMP-0008716-2, "CAP, CERM, 0.47 uF, 100 V, +/- 10%, X7R, 1206", Cap_Case=1206_180, Manufacturer=TDK, Supplier Part Number 1=445-2284-1-ND, TempCo=X7R, Tolerance_%=10%, Value1="0.007558 ohm", Value2=100V, ValueDisplayed=0.47uF
C10: library part CMP-0012470-3, "CAP, Film, 0.1 uF, 275V X2", Cap_Case="Radial 12.5x5.5x11", Manufacturer=Kemet, PartNumber=R46KF3100DQP1M, Tolerance_%=2%, Value1=Unknown, Value2=630V, ValueDisplayed=0.1uF
C11 C16: library part CMP-0007343-5, "CAP, CERM, 1 uF, 25 V, +/- 10%, X5R, 0603", Cap_Case=0603, Manufacturer=MuRata, Supplier Part Number 1=490-3897-1-ND, TempCo=X5R, Tolerance_%=10%, Value1=Unknown, Value2=25V, ValueDisplayed=1uF
C12: library part CMP-0064895-2, "CAP, AL, 22 uF, 50 V, +/- 20%, TH", Cap_Case=5x11, Manufacturer=Panasonic, Supplier Part Number 1=P5179-ND, Tolerance_%=20%, Value1=Unknown, Value2=50V, ValueDisplayed=22uF
C13: library part CMP-0006669-2, "CAP, CERM, 0.047 uF, 25 V, +/- 10%, X7R, 0402", Cap_Case=0402, Manufacturer=MuRata, Supplier Part Number 1=490-3254-1-ND, TempCo=X7R, Tolerance_%=10%, Value1=Unknown, Value2=25V, ValueDisplayed=0.047uF
C14: library part CMP-0007872-2, "CAP, CERM, 1 uF, 50 V, +/- 10%, X7R, 0805", Cap_Case=0805, Manufacturer=TDK, Supplier Part Number 1=445-14539-1-ND, TempCo=X7R, Tolerance_%=10%, Value1=Unknown, Value2=50V, ValueDisplayed=1uF
C15 C38: library part CMP-0006658-2, "CAP, CERM, 0.01 uF, 25 V, +/- 10%, X7R, 0402", Cap_Case=0402, Manufacturer=MuRata, Supplier Part Number 1=490-1312-1-ND, TempCo=X7R, Tolerance_%=10%, Value1=Unknown, Value2=25V, ValueDisplayed=0.01uF
C17: library part CMP-0006684-2, "CAP, CERM, 0.022 uF, 50 V, +/- 10%, X7R, 0402", Cap_Case=0402, Manufacturer=MuRata, Supplier Part Number 1=490-3884-1-ND, TempCo=X7R, Tolerance_%=10%, Value1=Unknown, Value2=50V, ValueDisplayed=0.022uF
C18: library part CMP-0006652-2, "CAP, CERM, 4700 pF, 16 V, +/- 10%, X7R, 0402", Cap_Case=0402, Manufacturer=MuRata, Supplier Part Number 1=GRM155R71C472KA01D-ND, TempCo=X7R, Tolerance_%=10%, Value1=Unknown, Value2=16V, ValueDisplayed=4700pF
C19: library part CMP-0077998-1, "CAP, CERM, 1500 pF, X1 440 VAC/Y1 250 VAC, +/- 20%, E, 8x6mm", Cap_Case=8x6mm, Manufacturer=MuRata, Supplier Part Number 1=490-16264-1-ND, TempCo=E, Tolerance_%=20%, ValueDisplayed=1500pF
C20: library part CMP-0007573-2, "CAP, CERM, 2.2 uF, 25 V, +/- 10%, X7R, 0805", Cap_Case=0805, Manufacturer=AVX, Supplier Part Number 1=478-5719-1-ND, TempCo=X7R, Tolerance_%=10%, Value1=Unknown, Value2=25V, ValueDisplayed=2.2uF
C21: library part CMP-0006708-2, "CAP, CERM, 3300 pF, 100 V, +/- 10%, X7R, 0402", Cap_Case=0402, Manufacturer=MuRata, Supplier Part Number 1=GRM155R72A332KA01D-ND, TempCo=X7R, Tolerance_%=10%, Value1=Unknown, Value2=100V, ValueDisplayed=3300pF
C23: library part CMP-0006614-2, "CAP, CERM, 0.1 uF, 50 V, +/- 20%, X5R, 0402", Cap_Case=0402, Manufacturer=MuRata, Supplier Part Number 1=GRM155R61H104ME14D-ND, TempCo=X5R, Tolerance_%=20%, Value1=Unknown, Value2=50V, ValueDisplayed=0.1uF
C24 C25 C200: library part CMP-0006410-2, "CAP, CERM, 100 pF, 50 V, +/- 5%, C0G/NP0, 0402", Cap_Case=0402, Manufacturer=MuRata, Supplier Part Number 1=81-GRM1555C1H101JA1D, TempCo=C0G/NP0, Tolerance_%=5%, Value1=Unknown, Value2=50V, ValueDisplayed=100pF
C26: library part CMP-0006424-2, "CAP, CERM, 18 pF, 50 V, +/- 5%, C0G/NP0, 0402", Cap_Case=0402, Manufacturer=MuRata, Supplier Part Number 1=14T3293, TempCo=C0G/NP0, Tolerance_%=5%, Value1=Unknown, Value2=50V, ValueDisplayed=18pF
C27: library part CMP-0006297-2, "CAP, CERM, 0.1 uF, 50 V, +/- 10%, X7R, 0402", Cap_Case=0402, Manufacturer=TDK, Supplier Part Number 1=445-5932-1-ND, TempCo=X7R, Tolerance_%=10%, Value1="0.039064 ohm", Value2=50V, ValueDisplayed=0.1uF
C29: library part CMP-0006249-2, "CAP, CERM, 220 pF, 50 V, +/- 1%, C0G/NP0, 0402", Cap_Case=0402, Manufacturer=TDK, Supplier Part Number 1=445-7015-1-ND, TempCo=C0G/NP0, Tolerance_%=1%, Value1=Unknown, Value2=50V, ValueDisplayed=220pF
C30: library part CMP-0006438-2, "CAP, CERM, 22 pF, 50 V, +/- 1%, C0G/NP0, 0402", Cap_Case=0402, Manufacturer=MuRata, Supplier Part Number 1=490-8589-1-ND, TempCo=C0G/NP0, Tolerance_%=1%, Value1=Unknown, Value2=50V, ValueDisplayed=22pF
C31 C100: library part CMP-0006683-2, "CAP, CERM, 2200 pF, 50 V, +/- 10%, X7R, 0402", Cap_Case=0402, Manufacturer=MuRata, Supplier Part Number 1=490-1305-1-ND, TempCo=X7R, Tolerance_%=10%, Value1=Unknown, Value2=50V, ValueDisplayed=2200pF
C32: library part CMP-0081668-2, "CAP, Aluminum Polymer, 680 µF, 25 V,+/- 20%, 0.29256 ohm, TH", Cap_Case=10x12mm, Manufacturer="Illinois Capacitor", Supplier Part Number 1=1572-1754-ND, Tolerance_%=20%, Value1="0.29256 ohm", Value2=25V, ValueDisplayed=680µF
C36: library part CMP-0007830-2, "CAP, CERM, 6.8 uF, 25 V, +/- 10%, X5R, 0805", Cap_Case=0805, Manufacturer=TDK, Supplier Part Number 1=445-5982-1-ND, TempCo=X5R, Tolerance_%=10%, Value1=Unknown, Value2=25V, ValueDisplayed=6.8uF
C101: library part CMP-0006673-2, "CAP, CERM, 1000 pF, 50 V, +/- 10%, X7R, 0402", Cap_Case=0402, Manufacturer=MuRata, Supplier Part Number 1=490-1303-1-ND, TempCo=X7R, Tolerance_%=10%, Value1=Unknown, Value2=50V, ValueDisplayed=1000pF
D1: library part CMP-0029244-3, "Diode, P-N-Bridge, 600 V, 4 A, Z4-D", Manufacturer="Comchip Technology", Value1=4A, Value2=0.95V
D2 D5: library part CMP-0029199-2, "Diode, Superfast Rectifier, 200 V, 1 A, 3.5x1.6mm", Manufacturer="Comchip Technology", Value1=1A, Value2=0.95V
D3: library part CMP-0005818-4, "Diode, TVS, Uni, 100V, SOD-123FL", Manufacturer=Littelfuse, PartNumber=SMF100A-T13, Value1=200W
D4: library part CMP-0080806-3, "Diode, Zener, 15 V, 150 mW, SOD-523F", Manufacturer="Comchip Technology", Power_W=150mW, Value1=0.15W
D6: library part CMP-0029162-1, "Diode, Ultrafast, 600 V, 1 A, AEC-Q101, SMAF", Manufacturer="Fairchild Semiconductor", Supplier Part Number 1=ES1JAFCT-ND, Value1=1A, Value2=1.7V
D7 D100: library part CMP-0005822-3, "Diode, TVS, Bi, 18 V, SOD-323", Manufacturer=Bourns, Value1=350W
D8: library part CMP-0005832-2, "Diode, Zener, 13 V, 200 mW, SOD-323", Manufacturer="Diodes Inc.", PartNumber=MMSZ5243BS-7-F, Power_W=200mW, Supplier Part Number 1=MMSZ5243BS-FDICT-ND, Value1=0.2W
D9: library part CMP-0080763-2, "Diode, Schottky, 40 V, 3 A, AEC-Q101, SOD-123W", Manufacturer=Nexperia, Value1=3A, Value2=0.54V
F1: library part CMP-0003561-1, "Fuse, 3.15 A, 250VAC/VDC, TH", Irating_A=3.15A, Manufacturer=Littelfuse, Supplier Part Number 1=F5504CT-ND
J1: library part CMP-0054818-1, "Connector, Receptacle, USB Type C, R/A", Color=Black, Current_A=3A, Manufacturer="Wurth Elektronik", Voltage_V=5V
J2: library part CMP-0054560-1, "Header, 50mil, 5x1, Gold, TH", Manufacturer="Sullins Connector Solutions", Supplier Part Number 1=S9014E-05-ND
J3: library part CMP-0054555-1, "Header, 50mil, 2x1, Gold, TH", Manufacturer="Sullins Connector Solutions", Supplier Part Number 1=S9014E-02-ND
L1: library part CMP-0087546-1, "WE-FI Leaded Toroidal Line Choke", Manufacturer=Wurth
L2: library part CMP-0086351-1, "Coupled inductor, 1.3 mH, 0.035 ohm, TH", Manufacturer="Renco Electronics", ValueDisplayed=1.3mH
L3: library part CMP-0060002-2, "Inductor, Wirewound, 22 uH, 0.49 A, 0.56 ohm, SMD", Manufacturer="Taiyo Yuden", Supplier Part Number 1=587-2439-1-ND, Value1="0.56 ohm", Value2=0.49A, ValueDisplayed=22uH
L4: library part 744042330, "Inductor, 1206, 0.68uH, 0.15 A, SMD", Manufacturer="Wurth Elektronik", Supplier Part Number 1=732-3658-1-ND, Value1="0.382 ohm", Value2=0.5A, ValueDisplayed=0.68µH
L5: library part CMP-0080751-1, "Inductor, Shielded, 1 µH, 11.5 A, 5.225 ohm, SMD", Manufacturer="Wurth Elektronik", Supplier Part Number 1=732-6176-1-ND, Value1="5.225 ohm", Value2=11.5A, ValueDisplayed=1µH
LINE NEUT: library part CMP-0055149-1, "Test Point, Multipurpose, White, TH", Color=White, Manufacturer=Keystone, Supplier Part Number 1=36-5012-ND
LOGO1: library part IEC_HighVoltage, "IEC 61010-1 High Voltage Warning"
Logo2: library part CMP-0074839-1
Logo3: library part CMP-0074769-1
LOGO4: library part CMP-0074837-1, "IEC 61010-1 Hot Surface Warning"
Q1: library part CMP-0000947-1, "MOSFET, N-CH, 100 V, 0.17 A, SOT-23", Alternate Manufacturer=None, Manufacturer="Fairchild Semiconductor", Supplier Part Number 1=BSS123NCT-ND, Value1=1, Value2="1.8 nC"
Q2: library part CMP-0001046-2, "MOSFET, N-CH, 150 V, 87 A, PG-TDSON-8", Alternate Manufacturer=None, Manufacturer="Infineon Technologies", Supplier Part Number 1=BSC093N15NS5ATMA1CT-ND, Value2="33 nC"
Q3 Q100: library part CMP-0000010-3, "MOSFET, P-CH, -20 V, -0.39 A, SOT-323", Alternate Manufacturer=None, Manufacturer="Infineon Technologies", Value1=1
Q4: library part CMP-0087214-1, "N-Channel 600V 6.8A (Tc) 5W (Tc) Surface Mount PG-SOT223", Manufacturer="Infineon Technologies"
Q5: library part CMP-0067574-2, "MOSFET, N-CH, Depletion Mode, 100 V, 0.17 A, AEC-Q101, SOT-23", Alternate Manufacturer=None, Manufacturer="Infineon Technologies", Supplier Part Number 1=BSS126H6327XTSA2CT-ND, Value1="? ohm", Value2="1.4 nC"
Q6: library part CMP-0000755-1, "MOSFET, N-CH, 50 V, 0.22 A, SOT-23", Alternate Manufacturer=None, Manufacturer="Fairchild Semiconductor", Supplier Part Number 1=BSS138CT-ND, Value2="1.7 nC"
Q7 Q101: library part CMP-0000774-1, "MOSFET, N-CH, 60 V, 0.31 A, SOT-323", Alternate Manufacturer=None, Manufacturer="Fairchild Semiconductor", Supplier Part Number 1=2N7002KWCT-ND, Value1=1
R1: library part CMP-0020501-3, "RES, 22, 5%, 0.125 W, AEC-Q200 Grade 0, 0805", Manufacturer=Vishay-Dale, Power_W=125mW, Supplier Part Number 1=541-22ACT-ND, TempCo="200 ppm/C", Tolerance_%=5%, Value2=0.125W, Value_Code=22R0, ValueDisplayed=22
R2: library part CMP-0026403-2, "RES, 49.9 k, 1%, 0.063 W, AEC-Q200 Grade 0, 0402", Manufacturer=Vishay-Dale, Power_W=63mW, Supplier Part Number 1=541-49.9KLCT-ND, TempCo="100 ppm/C", Tolerance_%=1%, Value2=0.063W, Value_Code=49k9, ValueDisplayed=49.9k
R3: library part CMP-0026281-2, "RES, 301, 1%, 0.063 W, AEC-Q200 Grade 0, 0402", Manufacturer=Vishay-Dale, Power_W=63mW, Supplier Part Number 1=541-301LCT-ND, TempCo="100 ppm/C", Tolerance_%=1%, Value2=0.063W, Value_Code=301R, ValueDisplayed=301
R4: library part CMP-0026942-3, "RES, 4.7, 5%, 0.063 W, AEC-Q200 Grade 0, 0402", Manufacturer=Vishay-Dale, Power_W=63mW, Supplier Part Number 1=541-4.7JCT-ND, TempCo="200 ppm/C", Tolerance_%=5%, Value2=0.063W, Value_Code=4R70, ValueDisplayed=4.7
R6: library part CMP-0026543-2, "RES, 75.0 k, 1%, 0.063 W, AEC-Q200 Grade 0, 0402", Manufacturer=Vishay-Dale, Power_W=63mW, Supplier Part Number 1=541-75.0KLCT-ND, TempCo="100 ppm/C", Tolerance_%=1%, Value2=0.063W, Value_Code=75k0, ValueDisplayed=75.0k
R8 R15 R41 R45: library part CMP-0026669-1, "RES, 150 k, 1%, 0.1 W, AEC-Q200 Grade 0, 0402", Manufacturer=Panasonic, Power_W=100mW, Supplier Part Number 1=P150KLCT-ND, TempCo="100 ppm/C", Tolerance_%=1%, Value2=0.1W, Value_Code=150k
R9: library part CMP-0026730-1, "RES, 30.1 k, 1%, 0.063 W, 0402", Manufacturer="Yageo America", Power_W=63mW, Supplier Part Number 1=311-30.1KLRCT-ND, TempCo="100 ppm/C", Tolerance_%=1%, Value2=0.063W, Value_Code=30k1, ValueDisplayed=30.1k
R10: library part CMP-0078669-1, "RES, 10.0 k, 1%, 0.063 W, 0402", Manufacturer="Yageo America", Power_W=63mW, Supplier Part Number 1=311-10.0KLRCT-ND, TempCo="100 ppm/C", Tolerance_%=1%, Value2=0.063W, Value_Code=10k0, ValueDisplayed=10.0k
R11: library part CMP-0026727-1, "RES, 1.00 M, 1%, 0.063 W, 0402", Manufacturer="Yageo America", Power_W=63mW, Supplier Part Number 1=311-1.00MLRCT-ND, TempCo="100 ppm/C", Tolerance_%=1%, Value2=0.063W, Value_Code=1M00, ValueDisplayed=1.00M
R12: library part CMP-0025985-3, "RES, 121, 1%, 0.063 W, AEC-Q200 Grade 0, 0402", Manufacturer=Vishay-Dale, Power_W=63mW, Supplier Part Number 1=541-121LCT-ND, TempCo="100 ppm/C", Tolerance_%=1%, Value2=0.063W, Value_Code=121R, ValueDisplayed=121
R13 R14 R20: library part CMP-0026100-2, "RES, 1.00 M, 1%, 0.063 W, AEC-Q200 Grade 0, 0402", Manufacturer=Vishay-Dale, Power_W=63mW, Supplier Part Number 1=541-1.00MLCT-ND, TempCo="100 ppm/C", Tolerance_%=1%, Value2=0.063W, Value_Code=1M00, ValueDisplayed=1.00M
R16: library part CMP-0026573-2, "RES, 825, 1%, 0.063 W, AEC-Q200 Grade 0, 0402", Manufacturer=Vishay-Dale, Power_W=63mW, Supplier Part Number 1=541-825LCT-ND, TempCo="100 ppm/C", Tolerance_%=1%, Value2=0.063W, Value_Code=825R, ValueDisplayed=825
R17 R25 R100: library part CMP-0026435-2, "RES, 511 k, 1%, 0.063 W, AEC-Q200 Grade 0, 0402", Manufacturer=Vishay-Dale, Power_W=63mW, Supplier Part Number 1=541-511KLCT-ND, TempCo="100 ppm/C", Tolerance_%=1%, Value2=0.063W, Value_Code=511k
R18 R23: library part CMP-0026071-3, "RES, 1.00 k, 1%, 0.063 W, AEC-Q200 Grade 0, 0402", Manufacturer=Vishay-Dale, Power_W=63mW, Supplier Part Number 1=541-1.00KLCT-ND, TempCo="100 ppm/C", Tolerance_%=1%, Value2=0.063W, Value_Code=1k00, ValueDisplayed=1.00k
R19: library part CMP-0026589-2, "RES, 8.25 k, 1%, 0.063 W, AEC-Q200 Grade 0, 0402", Manufacturer=Vishay-Dale, Power_W=63mW, Supplier Part Number 1=541-8.25KLCT-ND, TempCo="100 ppm/C", Tolerance_%=1%, Value2=0.063W, Value_Code=8k25, ValueDisplayed=8.25k
R21: library part CMP-0026162-2, "RES, 20.0 k, 1%, 0.063 W, AEC-Q200 Grade 0, 0402", Manufacturer=Vishay-Dale, Power_W=63mW, Supplier Part Number 1=541-20.0KLCT-ND, TempCo="100 ppm/C", Tolerance_%=1%, Value2=0.063W, Value_Code=20k0, ValueDisplayed=20.0k
R22: library part CMP-0017277-2, "RES, 0.15, 1%, 0.5 W, 1206", Manufacturer=Panasonic, Power_W=500mW, Supplier Part Number 1=P16006CT-ND, TempCo="250 ppm/C", Tolerance_%=1%, Value2=0.5W, Value_Code=R150, ValueDisplayed=0.15
R24 R36: library part CMP-0026304-2, "RES, 34.0 k, 1%, 0.063 W, AEC-Q200 Grade 0, 0402", Manufacturer=Vishay-Dale, Power_W=63mW, Supplier Part Number 1=541-34.0KLCT-ND, TempCo="100 ppm/C", Tolerance_%=1%, Value2=0.063W, Value_Code=34k0, ValueDisplayed=34.0k
R26: library part CMP-0026321-2, "RES, 392 k, 1%, 0.063 W, AEC-Q200 Grade 0, 0402", Manufacturer=Vishay-Dale, PartNumber=CRCW0402393KFKED, Power_W=63mW, Supplier Part Number 1=541-383KLCT-ND, TempCo="100 ppm/C", Tolerance_%=1%, Value2=0.063W, Value_Code=392k
R28: library part CMP-0026574-2, "RES, 82.5 k, 1%, 0.063 W, AEC-Q200 Grade 0, 0402", Manufacturer=Vishay-Dale, Power_W=63mW, Supplier Part Number 1=541-82.5KLCT-ND, TempCo="100 ppm/C", Tolerance_%=1%, Value2=0.063W, Value_Code=82k5, ValueDisplayed=82.5k
R32: library part CMP-0026063-3, "RES, 191 k, 1%, 0.063 W, AEC-Q200 Grade 0, 0402", Manufacturer=Vishay-Dale, Power_W=63mW, Supplier Part Number 1=541-191KLCT-ND, TempCo="100 ppm/C", Tolerance_%=1%, Value2=0.063W, Value_Code=191k
R37: library part CMP-0026510-2, "RES, 69.8 k, 1%, 0.063 W, AEC-Q200 Grade 0, 0402", Manufacturer=Vishay-Dale, Power_W=63mW, Supplier Part Number 1=541-69.8KLCT-ND, TempCo="100 ppm/C", Tolerance_%=1%, Value2=0.063W, Value_Code=69k8, ValueDisplayed=69.8k
R38: library part CMP-0026658-1, "RES, 10.0 k, 1%, 0.1 W, 0402", Manufacturer=Panasonic, Power_W=100mW, Supplier Part Number 1=P10.0KLCT-ND, TempCo="100 ppm/C", Tolerance_%=1%, Value2=0.1W, Value_Code=10k0, ValueDisplayed=10.0k
R39: library part CMP-0025951-3, "RES, 100, 1%, 0.063 W, AEC-Q200 Grade 0, 0402", Manufacturer=Vishay-Dale, Power_W=63mW, Supplier Part Number 1=541-100LCT-ND, TempCo="100 ppm/C", Tolerance_%=1%, Value2=0.063W, Value_Code=100R, ValueDisplayed=100
R40: library part CMP-0027004-2, "RES, 0, 5%, 0.063 W, 0402", Manufacturer="Yageo America", Power_W=63mW, Supplier Part Number 1=311-0.0JRCT-ND, TempCo="200 ppm/C", Tolerance_%=5%, Value2=0.063W, Value_Code=0000, ValueDisplayed=0
R42: library part CMP-0026196-2, "RES, 24.9 k, 1%, 0.063 W, AEC-Q200 Grade 0, 0402", Manufacturer=Vishay-Dale, Power_W=63mW, Supplier Part Number 1=541-24.9KLCT-ND, TempCo="100 ppm/C", Tolerance_%=1%, Value2=0.063W, Value_Code=24k9, ValueDisplayed=24.9k
R43: library part CMP-0026027-3, "RES, 15.0 k, 1%, 0.063 W, AEC-Q200 Grade 0, 0402", Manufacturer=Vishay-Dale, Power_W=63mW, Supplier Part Number 1=541-15.0KLCT-ND, TempCo="100 ppm/C", Tolerance_%=1%, Value2=0.063W, Value_Code=15k0, ValueDisplayed=15.0k
R101: library part CMP-0020510-3, "RES, 2.0 k, 5%, 0.125 W, AEC-Q200 Grade 0, 0805", Manufacturer=Vishay-Dale, Power_W=125mW, Supplier Part Number 1=541-2.0KACT-ND, TempCo="200 ppm/C", Tolerance_%=5%, Value2=0.125W, Value_Code=2k00, ValueDisplayed=2.0k
R200: library part CMP-0026555-2, "RES, 7.50 k, 1%, 0.063 W, AEC-Q200 Grade 0, 0402", Manufacturer=Vishay-Dale, Power_W=63mW, Supplier Part Number 1=541-7.50KLCT-ND, TempCo="100 ppm/C", Tolerance_%=1%, Value2=0.063W, Value_Code=7k50, ValueDisplayed=7.50k
RT1: library part CMP-0002523-3, "Thermistor NTC, 47k ohm, 5%, 0603", Manufacturer=MuRata, Power_W=100mW, Supplier Part Number 1=490-2428-1-ND, Tolerance_%=5%
T1: library part CMP-0086869-1, "Transformer", Manufacturer="Würth Elektronik"
TP1: library part CMP-0055137-1, "Test Point, Miniature, Red, TH", Color=Red, Manufacturer=Keystone, Supplier Part Number 1=36-5000-ND
TP2: library part CMP-0055147-1, "Test Point, Multipurpose, Red, TH", Color=Red, Manufacturer=Keystone, PartNumber=5010, Supplier Part Number 1=36-5010-ND
TP3: library part CMP-0055138-1, "Test Point, Miniature, Black, TH", Color=Black, Manufacturer=Keystone, Supplier Part Number 1=36-5001-ND
U1: library part CMP-0086802-1, "FAST TURN-OFF INTELLIGENT RECTIF", Manufacturer="Monolithic Power Systems"
U2: library part CMP-0077706-1, "3-kVRMS Single-Channel Isolated Gate Drivers, D0008B (SOIC-8)", Alternate Manufacturer="Texas Instruments", Alternate PartNumber=UCC5350SBD
U3: library part CMP-0078736-2, "600-V 12-A Single Channel GaN Power Stage, RWH0032A (VQFN-32)", Alternate Manufacturer="Texas Instruments", Alternate PartNumber=LMG3411R150, Operating Temperature Range="-40 to 125 C"
U4: library part CMP-0085889-2, "Small-Size Micropower Low-Voltage Comparator, DCK0005A (SOT-SC70-5)", Alternate Manufacturer="Texas Instruments", Alternate PartNumber=TLV7021DCKT, Operating Temperature Range="-40 to 125 C", Rating=Catalog
U5: library part CMP-0006160-3, "Optocoupler, 5 kV, 63-125% CTR, SMT", Manufacturer=Vishay-Semiconductor, Supplier Part Number 1=VOL618A-2TCT-ND, Voltage_Isolation_Vrms=5kV
U6: library part CMP-0014005-4, "Active-Clamp Flyback Controller, RTE0016C (WQFN-16)", Alternate Manufacturer="Texas Instruments", Alternate PartNumber=UCC28780RTE
U8 U9: library part CMP-0073591-3, "Automotive 1-Channel Ultra-Low-Capacitance IEC ESD Protection Diode, DPY0002A (X1SON-2)", Alternate Manufacturer="Texas Instruments", Alternate PartNumber=TPD1E05U06QDPYTQ1, Operating Temperature Range="-40 to 125 C", Rating=Automotive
